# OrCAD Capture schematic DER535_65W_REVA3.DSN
size C; title: DER535_65W_revD
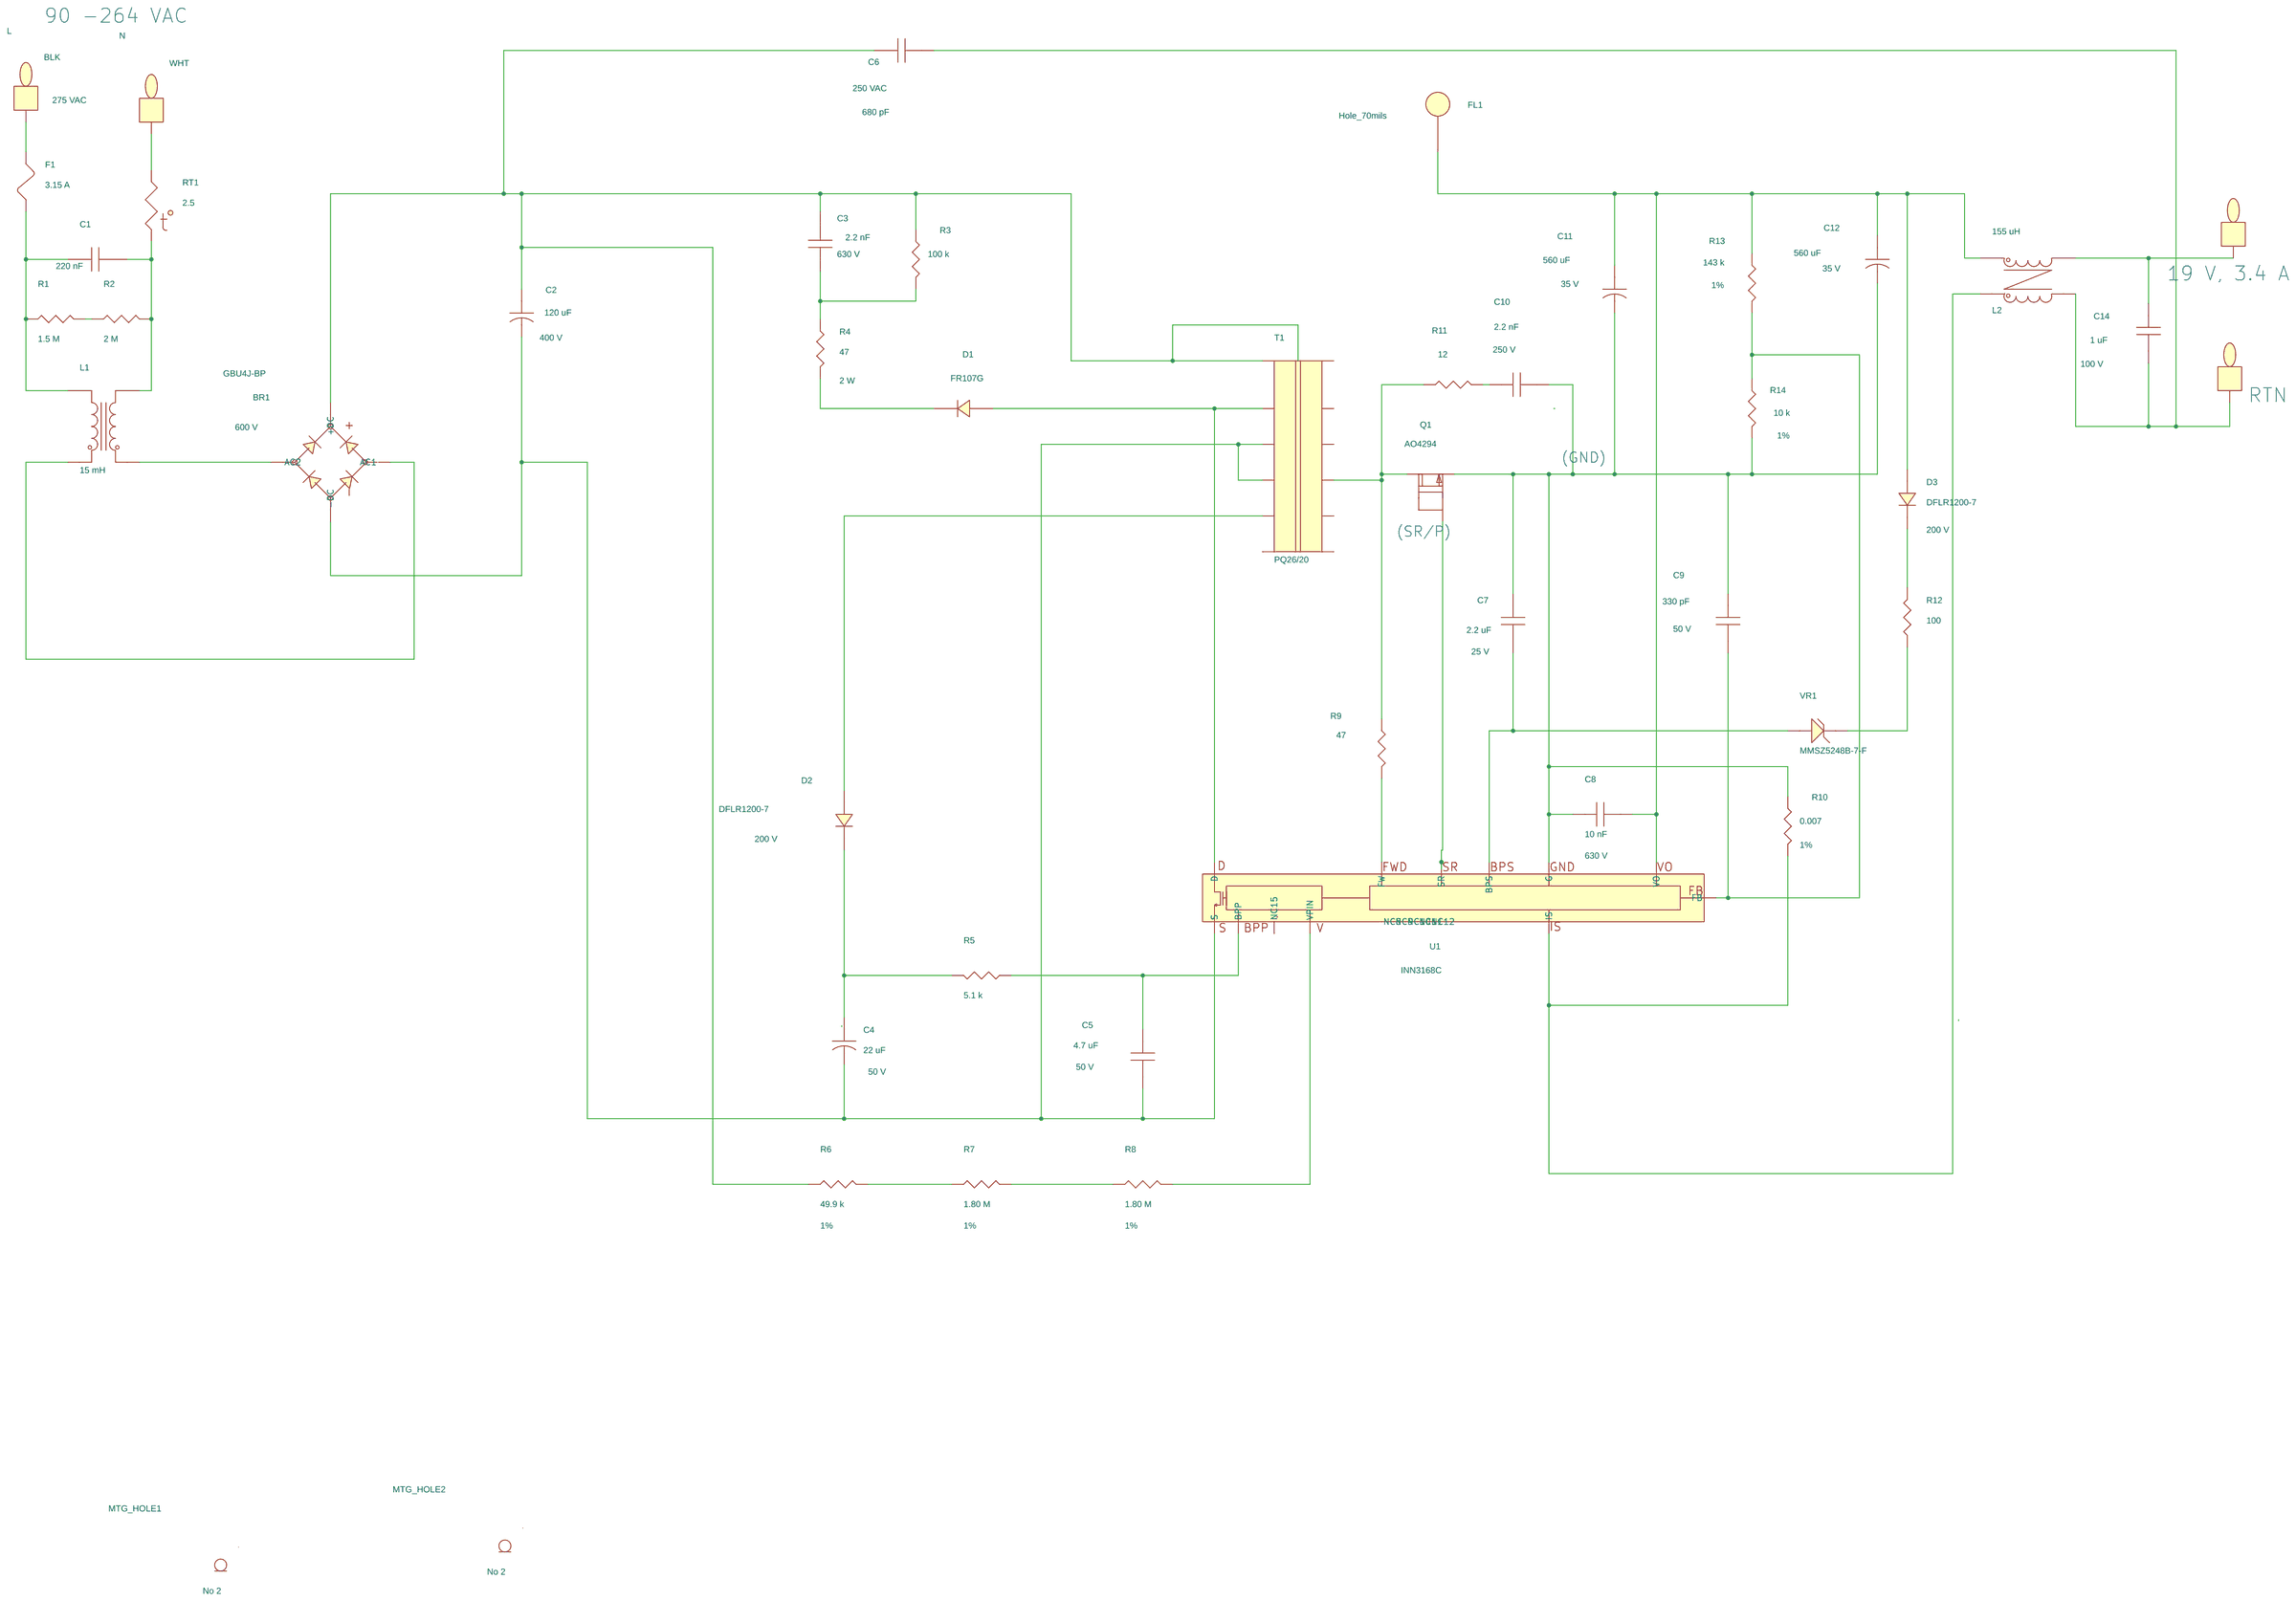
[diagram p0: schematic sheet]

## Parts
BR1  GBU4J-BP  [pidaxbridgegbu8]
C1  220 nF  [pinpxcaprad720x340590040]
C2  120 uF  [pipolcapd710ls3000401400lhoriz]
C3  2.2 nF  [pismc1206]
C4  22 uF  [pipolcapclyd200ls80030]
C5  4.7 uF  [pismc0805]
C6  680 pF  [pinpycaprad470x210ls380040]
C7  2.2 uF  [pismc0805]
C8  10 nF  [pismc1206]
C9  330 pF  [pismc0603]
C10  2.2 nF  [pismc0805]
C11  560 uF  [pipolcapcyld400ls200040]
C12  560 uF  [pipolcapcyld400ls200040]
C14  1 uF  [pismc0805]
D1  FR107G  [pidv200x110x040do41]
D2  DFLR1200-7  [pismddflr120012]
D3  DFLR1200-7  [pismddflr120012]
F1  3.15 A  [pi_rst_microfuse]
FL1  Hole_70mils  [pi_hole_70mil]
L  BLK  [pitpkeystone125x125]
L1  15 mH  [piind4p944x650ls492x394031]
L2  155 uH  [pi_toroid_cmc_DER535]
MTG_HOLE1  No 2  [pimtghole2]
MTG_HOLE2  No 2  [pimtghole2]
N  WHT  [pitpkeystone125x125]
Q1  AO4294  [pismso8]
R1  1.5 M  [pismr1206]
R2  2 M  [pismr1206]
R3  100 k  [pismr1206]
R4  47  [PI_2W_VRES240LS200D040]
R5  5.1 k  [pismr0603]
R6  49.9 k  [pismr0805]
R7  1.80 M  [pismr1206]
R8  1.80 M  [pismr1206]
R9  47  [pismr0603]
R10  0.007  [pismr0805]
R11  12  [pismr1206]
R12  100  [pismr0603]
R13  143 k  [pismr0805]
R14  10 k  [pismr0603]
RT1  2.5  [pi_rad150x300ls200d030]
T1  PQ26/20  [pi_bobbin_bpq26_20_12p]
TP3  RED  [pitpkeystone125x125]
TP4  BLK  [pitpkeystone125x125]
U1  INN3168C  [pi_ic_insop_24b]
VR1  MMSZ5248B-7-F  [pi_sm_sod-123_12]

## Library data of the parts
BR1 = DISCRETE_BRIDGE_+~~-: Disp_Voltage: 600 V; Part Number: 15-00721-00
C1 = CAP_NP: Disp_Voltage: 275 VAC; Part Number: 20-00386-00; Voltage: 275 VAC
C2 = CAP_POL: Disp_Voltage: 400 V; FPLIST: pipolcapclyd710ls300040,pipolcapd710ls3000401400lhoriz; Part Number: 20-00685-00; Voltage: 400 V
C3 = CAP_NP: Disp_Voltage: 630 V; Part Number: 20-08609-00; Voltage: 630 V
C4 = CAP_POL: ALT_SYMBOLS: pipolcapclyd200ls80030h; Disp_Voltage: 50 V; FPLIST: pipolcapclyd200ls80030,pipolcapclyd200ls80030h; Part Number: 20-00056-00; Voltage: 50 V
C5 = CAP_NP: Disp_Voltage: 50 V; Part Number: 20-01130-00; Voltage: 50 V
C6 = CAP_NP: COMPGROUP: 3; Disp_Voltage: 250 VAC; PCB Editor PCBFP: pinpycaprad540x290ls400040; Part Number: 20-00374-00; Voltage: 250 VAC
C7 = CAP_NP: Disp_Voltage: 25 V; Part Number: 20-08603-00; Voltage: 25 V
C8 = CAP_NP: Disp_Voltage: 630 V; Part Number: 20-00939-00; Voltage: 630 V
C9 = CAP_NP: Disp_Voltage: 50 V; Part Number: 20-08676-00; Voltage: 50 V
C10 = CAP_NP: Disp_Voltage: 250 V; PCB Editor PCBFP: pismc0603; Part Number: 20-08766-00; Voltage: 250 V
C11 C12 = CAP_POL: ALT_SYMBOLS: pipolcapcyld400ls2000401000h; COMPGROUP: 3; Disp_Voltage: 35 V; FPLIST: pipolcapcyld400ls200040,pipolcapcyld400ls2000401000h; Part Number: 20-00049-00; Voltage: 35 V
C14 = CAP_NP: Disp_Voltage: 100 V; Part Number: 20-01324-00; Voltage: 100 V
D1 = DIODE: ALT_SYMBOLS: pidax475x125040do41,pidv200x110x040do41wbead,pidax390x125040do41; FPLIST: pidv200x110x040do41,pidax475x125040do41,pidv200x110x040do41wbead,pidax390x125040do41; Part Number: 15-00646-00
D2 = DIODE: COMPGROUP: 1; Disp_Voltage: 200 V; Part Number: 15-01019-00
D3 = DIODE: Disp_Voltage: 200 V; Part Number: 15-01019-00
F1 = FUSE: ALT_SYMBOLS: pirstmicrofusehoz; FPLIST: pi_rst_microfuse,pirstmicrofusehoz; Part Number: 40-00020-00
FL1 = FlyingLead: Part Number: 35-00282-00
L TP4 = TESTPOINT: Part Number: 35-00042-00
L1 = INDUCTOR_4P_revD: Part Number: 30-00416-00
L2 = TORRID_4P_14_23: Part Number: 32-00344-00
MTG_HOLE1 MTG_HOLE2 = MTG_HOLE_2-56: Part Number: 66-00108-00
N = TESTPOINT: Part Number: 35-00044-00
Q1 = FET_N_SGD_123_4_5678: Part Number: 50-00226-00
R1 = R: Part Number: 05-01425-00
R2 = R: Part Number: 05-01428-00
R3 = R: Part Number: 05-01400-00
R4 = R: ALT_SYMBOLS: PI_2W_RES240LS500D040,pi_2w_resd145ls455d040; Disp_Power: 2 W; FPLIST: PI_2W_VRES240LS200D040,PI_2W_RES240LS500D040,pi_2w_resd145ls455d040; Part Number: 05-05559-00
R5 = R: Part Number: 05-01705-00
R6 = R: Disp_Tol: 1%; Part Number: 05-00751-00
R7 R8 = R: Disp_Tol: 1%; Part Number: 05-03155-00
R9 = R: Part Number: 05-01656-00
R10 = R: Disp_Tol: 1%; Part Number: 05-06438-00
R11 = R: Part Number: 05-01306-00
R12 = R: Part Number: 05-01664-00
R13 = R: Disp_Tol: 1%; Part Number: 05-00795-00
R14 = R: Disp_Tol: 1%; Part Number: 05-03182-00
RT1 = THERMISTOR: ALT_SYMBOLS: pirad400x300ls200040_h; FPLIST: pi_rad150x300ls200d030,pirad400x300ls200040_h; Part Number: 90-00040-00
T1 = BPQ26_20_12P_GENERIC: Part Number: 25-00025-00
TP3 = TESTPOINT: Part Number: 35-00043-00
U1 = DEV_InSOP_0: Part Number: 10-00915-00
VR1 = DIODE_ZENER: Part Number: 15-01105-00

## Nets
NC8: U1.8(NC8)
NC9: U1.9(NC9)
NC10: U1.10(NC10)
NC11: U1.11(NC11)
NC12: U1.12(NC12)
NC15: U1.15(NC15)
N2987702: BR1.1(+DC) C2.1 C3.2 C6.1 R3.1 R6.1 T1.1
N2987790: BR1.2(AC1) L1.1
N2987798: N.1 RT1.1
N2987826: F1.2 L.1
N10910152: R9.2 U1.7(FW)
N10910164: C3.1 R3.2 R4.2
N10910168: L2.2 R10.2 U1.1(IS)
N10910222: C7.1 C8.1 C9.1 C10.2 C11.2 C12.2 Q1.1(S) R10.1 R14.2 U1.2(G)
N10910248: Q1.4(G) U1.5(SR)
N10910298: C5.1 R5.2 U1.14(BPP)
N10910306: C8.2 C11.1 C12.1 D3.2 FL1.1 L2.1 R13.1 U1.6(VO)
N10910326: BR1.4(-DC) C2.2 C4.2 C5.2 T1.3 T1.4 U1.16(S)
N10910384: C9.2 R13.2 R14.1 U1.3(FB)
N10910392: R8.2 U1.13(VPIN)
N10910464: D2.2 T1.5
N10910558: C10.1 R11.1
N10910618: R7.2 R8.1
N10910664: C6.2 C14.2 L2.3 TP4.1
N10911024: C7.2 U1.4(BPS) VR1.2
N10911106: C4.1 D2.1 R5.1
N10913618: D1.1 R4.1
N10913908: D1.2 T1.2 U1.24(D)
N10921396: C1.2 L1.3 R2.2 RT1.2
N10932979: C14.1 L2.4 TP3.1
N10933272: Q1.5(D) R9.1 R11.2 T1.9
N10975944: C1.1 F1.1 L1.2 R1.1
N10976231: BR1.3(AC2) L1.4
N10995479: R1.2 R2.1
N11000162: R12.1 VR1.1
N11000879: R6.2 R7.1
N11102383: D3.1 R12.2

Not connected (* = marked no-connect by the designer): MTG_HOLE1 1; MTG_HOLE2 1; Q1 2(S2) 3(S3) 6(D6) 7(D7) 8(D8); T1 6 7 8 10 11 12

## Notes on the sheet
- 90 -264 VAC
- 19 V, 3.4 A
- RTN
- (GND)
- (SR/P)
